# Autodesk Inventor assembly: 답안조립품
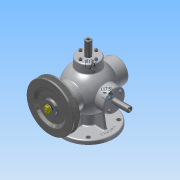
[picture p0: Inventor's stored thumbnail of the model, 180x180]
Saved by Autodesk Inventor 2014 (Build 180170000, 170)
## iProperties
Created: 2016-01
Part Number: 답안조립품
Document SubType Name: Assembly
Designer: Administrator
Author: Administrator
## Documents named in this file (17)
- C:\Users\Administrator\Desktop\360108V1010\답안조립품.iam
- C:\Users\Administrator\Desktop\360108V1010\본체.ipt
- C:\Users\Administrator\Desktop\360108V1010\V-벨트풀리.ipt
- C:\Users\Administrator\Desktop\360108V1010\너트-M8x1.ipt
- C:\Users\Administrator\Desktop\360108V1010\뒤커버.ipt
- C:\Users\Administrator\Desktop\360108V1010\베어링- 6202.ipt
- C:\Users\Administrator\Desktop\360108V1010\본체커버.ipt
- C:\Users\Administrator\Desktop\360108V1010\볼트 M4x0.7.ipt
- C:\Users\Administrator\Desktop\360108V1010\스프링1.ipt
- C:\Users\Administrator\Desktop\360108V1010\스프링2.ipt
- C:\Users\Administrator\Desktop\360108V1010\슬라이드 커버.ipt
- C:\Users\Administrator\Desktop\360108V1010\슬라이드.ipt
- C:\Users\Administrator\Desktop\360108V1010\앞커버.ipt
- C:\Users\Administrator\Desktop\360108V1010\오일실.ipt
- C:\Users\Administrator\Desktop\360108V1010\와셔 8x17.ipt
- C:\Users\Administrator\Desktop\360108V1010\축.ipt
- C:\Users\Administrator\Desktop\360108V1010\키-4x4.ipt
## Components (18 placed, 2 different names)
1. V-벨트풀리:1 — 각도:2, 각도:4
2. M4x0.7x12:5
3. M4x0.7x12:2
4. M4x0.7x12:9
5. M4x0.7x12:10
6. M4x0.7x12:11
7. M4x0.7x12:4
8. M4x0.7x12:12
9. M4x0.7x12:13
10. M4x0.7x12:14
11. M4x0.7x12:3
12. M4x0.7x12:15
13. M4x0.7x12:16
14. M4x0.7x12:17
15. M4x0.7x12:1
16. M4x0.7x12:18
17. M4x0.7x12:19
18. M4x0.7x12:20
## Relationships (2: Angle 2)
- 각도:2 [Angle]: V-벨트풀리:1
- 각도:4 [Angle]: V-벨트풀리:1
